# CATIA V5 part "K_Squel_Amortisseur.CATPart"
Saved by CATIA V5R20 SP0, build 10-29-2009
Part number: Squelette_Amortisseur
Publications: "Plan.3", "Point.2", "Plan.5"
Bounding box of the stored display mesh (mm): x -137 to -48, y -66.066 to 148.187, z -108.187 to 106.066
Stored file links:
  G:\Khaled_CFAO_2011\ST2M\ST2M_GR2\plakomicki\Khaled\CAD_ThinkMOTION\K_Squel_Amortisseur.CATPart
  G:\Khaled_CFAO_2011\ST2M\ST2M_GR2\plakomicki\Khaled\CAD_ThinkMOTION\K_Squelette.CATProduct
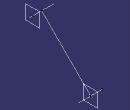
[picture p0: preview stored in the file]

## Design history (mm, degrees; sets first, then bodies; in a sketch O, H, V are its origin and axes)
External parameters (linked from other documents)
  External.Longueur_structure = 300 mm
Set1
  Point1: linked copy from another document
  Plane1: linked copy from another document
Set2
  Line1 "axe_pivot_amortisseur_bras": type PtDir, RefPoint Point1, Direction yz-plane, Start 0, End 39
  Plane2: type Angle, RefPlane Plane1, Direction Line1, Angle -45
  Plane3 "Plan_longueur_amortisseur": type Offset, RefPlane Plane2, Offset 303 {= External.Longueur_structure +3mm}
  Point2: type OnPlane, Support Plane3, RefPoint Point1, H 0, V 0, Direction (-1, 0, 0)
  Line2 "longueur_amortisseur": type PtPt, FirstPoint Point1, SecondPoint Point2
  Line3: type PtDir, RefPoint Point2, Direction yz-plane, Start 0, End -50
  Plane4: type OffsetPt, RefPlane yz-plane, RefPoint vertex of Line1
  Plane5: type OffsetPt, RefPlane yz-plane, RefPoint Point2
Body1 (main body)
